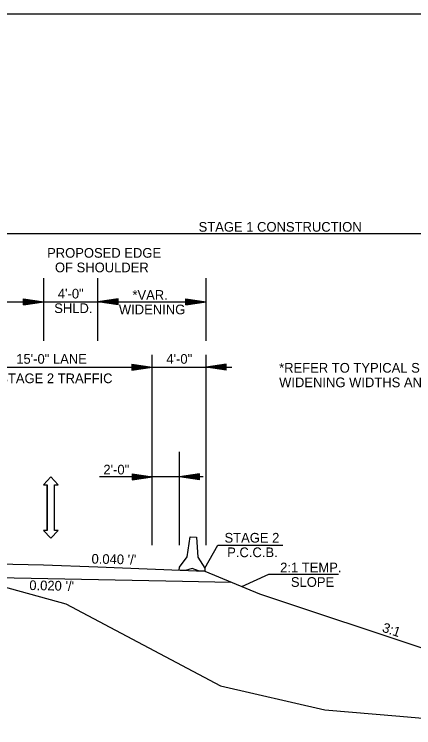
# Model space of a CAD drawing. Extents: x 1807779 to 1818251, y 673292 to 678849.
# Drawn here: x 1813576 to 1813872, y 676849 to 677379 of the extents above; entities that cross this region are included whole.
import ezdxf

# ---------------------------------------------------------------- set-up
doc = ezdxf.new("R2010")
doc.units = 0
for name, color, linetype in [('Default', 7, 'Continuous'), ('Dimensions', 7, 'Continuous'), ('DSN_DRFT_Guideline-No-Plot', 7, 'Continuous'), ('EX_TERRAIN', 7, 'Continuous'), ('Level 1', 7, 'Continuous')]:
    doc.layers.add(name, color=color, linetype=linetype)

msp = doc.modelspace()

# ---------------------------------------------------------------- linework, layer by layer
at = {"layer": 'Default'}
for p, q in [((1813487.67, 676972.49), (1813597.65, 676970.29)), ((1813597.65, 676970.29), (1813637.9, 676968.68)), ((1813637.9, 676968.68), (1813717.07, 676965.51)), ((1813717.07, 676965.51), (1813757.78, 676948.7)), ((1813487.67, 676962.49), (1813700.59, 676958.23)), ((1813700.59, 676958.23), (1813736.44, 676957.51)), ((1813757.78, 676948.7), (1814046.76, 676852.37))]:
    msp.add_line(p, q, dxfattribs=at)
at = {"layer": 'Dimensions'}
for p, q in [((1813487.67, 677216.24), (1814046.76, 677216.24)), ((1813597.67, 677136.5), (1813597.67, 677183.13)), ((1813637.9, 677136.5), (1813637.9, 677183.13)), ((1813718.05, 677136.5), (1813718.05, 677183.13)), ((1813582.67, 677167.67), (1813597.67, 677165.42)), ((1813582.67, 677163.17), (1813582.67, 677167.67)), ((1813582.67, 677167.29), (1813595.17, 677165.42)), ((1813582.67, 677166.91), (1813592.59, 677165.42)), ((1813582.67, 677166.54), (1813590.09, 677165.42)), ((1813582.67, 677166.15), (1813587.55, 677165.42)), ((1813582.67, 677165.77), (1813585.04, 677165.42)), ((1813652.9, 677167.67), (1813637.9, 677165.42)), ((1813652.9, 677167.29), (1813640.41, 677165.42)), ((1813652.9, 677166.91), (1813642.99, 677165.42)), ((1813652.9, 677166.54), (1813645.48, 677165.42)), ((1813652.9, 677166.15), (1813648.03, 677165.42)), ((1813652.9, 677165.77), (1813650.53, 677165.42)), ((1813652.9, 677163.17), (1813652.9, 677167.67)), ((1813703.05, 677167.67), (1813718.05, 677165.42)), ((1813703.05, 677163.17), (1813703.05, 677167.67)), ((1813703.05, 677167.29), (1813715.55, 677165.42)), ((1813703.05, 677166.91), (1813712.97, 677165.42)), ((1813703.05, 677166.54), (1813710.47, 677165.42)), ((1813703.05, 677166.15), (1813707.93, 677165.42)), ((1813703.05, 677165.77), (1813705.42, 677165.42)), ((1813487.67, 677165.42), (1813597.67, 677165.42)), ((1813582.67, 677163.17), (1813597.67, 677165.42)), ((1813582.67, 677164.69), (1813587.55, 677165.42)), ((1813582.67, 677163.93), (1813592.59, 677165.42)), ((1813582.67, 677163.54), (1813595.17, 677165.42)), ((1813582.67, 677164.3), (1813590.09, 677165.42)), ((1813582.67, 677165.07), (1813585.04, 677165.42)), ((1813597.67, 677165.42), (1813718.05, 677165.42)), ((1813652.9, 677163.17), (1813637.9, 677165.42)), ((1813652.9, 677163.54), (1813640.41, 677165.42)), ((1813652.9, 677163.93), (1813642.99, 677165.42)), ((1813652.9, 677164.3), (1813645.48, 677165.42)), ((1813652.9, 677164.69), (1813648.03, 677165.42)), ((1813652.9, 677165.07), (1813650.53, 677165.42)), ((1813703.05, 677163.17), (1813718.05, 677165.42)), ((1813703.05, 677164.69), (1813707.93, 677165.42)), ((1813703.05, 677163.93), (1813712.97, 677165.42)), ((1813703.05, 677163.54), (1813715.55, 677165.42)), ((1813703.05, 677164.3), (1813710.47, 677165.42)), ((1813703.05, 677165.07), (1813705.42, 677165.42)), ((1813678.05, 676984.76), (1813678.05, 677126.17)), ((1813718.05, 676984.76), (1813718.05, 677126.17)), ((1813663.05, 677119.2), (1813678.05, 677116.95)), ((1813663.05, 677119.2), (1813663.05, 677114.7)), ((1813663.05, 677118.82), (1813675.55, 677116.95)), ((1813663.05, 677118.44), (1813672.97, 677116.95)), ((1813663.05, 677118.07), (1813670.47, 677116.95)), ((1813733.05, 677119.2), (1813718.05, 677116.95)), ((1813733.05, 677118.82), (1813720.56, 677116.95)), ((1813733.05, 677118.44), (1813723.14, 677116.95)), ((1813733.05, 677118.07), (1813725.64, 677116.95)), ((1813733.05, 677114.7), (1813733.05, 677119.2)), ((1813528.05, 677116.95), (1813678.05, 677116.95)), ((1813663.05, 677117.68), (1813667.93, 677116.95)), ((1813663.05, 677117.3), (1813665.42, 677116.95)), ((1813663.05, 677114.7), (1813678.05, 677116.95)), ((1813663.05, 677116.21), (1813667.93, 677116.95)), ((1813663.05, 677115.46), (1813672.97, 677116.95)), ((1813663.05, 677115.07), (1813675.55, 677116.95)), ((1813663.05, 677115.83), (1813670.47, 677116.95)), ((1813663.05, 677116.6), (1813665.42, 677116.95)), ((1813678.05, 677116.95), (1813737.3, 677116.95)), ((1813733.05, 677114.7), (1813718.05, 677116.95)), ((1813733.05, 677115.07), (1813720.56, 677116.95)), ((1813733.05, 677115.46), (1813723.14, 677116.95)), ((1813733.05, 677115.83), (1813725.64, 677116.95)), ((1813733.05, 677117.68), (1813728.18, 677116.95)), ((1813733.05, 677116.22), (1813728.18, 677116.95)), ((1813733.05, 677117.3), (1813730.68, 677116.95)), ((1813733.05, 677116.6), (1813730.68, 677116.95)), ((1813698.31, 676984.76), (1813698.31, 677054.21)), ((1813715.9, 677035.48), (1813639.13, 677035.48)), ((1813663.31, 677037.73), (1813678.31, 677035.48)), ((1813663.31, 677037.73), (1813663.31, 677033.23)), ((1813663.31, 677037.36), (1813675.81, 677035.48)), ((1813663.31, 677036.98), (1813673.23, 677035.48)), ((1813663.31, 677036.6), (1813670.73, 677035.48)), ((1813663.31, 677036.21), (1813668.19, 677035.48)), ((1813663.31, 677035.84), (1813665.68, 677035.48)), ((1813663.31, 677033.23), (1813678.31, 677035.48)), ((1813663.31, 677034.75), (1813668.19, 677035.48)), ((1813663.31, 677033.99), (1813673.23, 677035.48)), ((1813663.31, 677033.61), (1813675.81, 677035.48)), ((1813663.31, 677034.37), (1813670.73, 677035.48)), ((1813663.31, 677035.13), (1813665.68, 677035.48)), ((1813713.31, 677037.73), (1813698.31, 677035.48)), ((1813713.31, 677033.23), (1813698.31, 677035.48)), ((1813713.31, 677037.36), (1813700.82, 677035.48)), ((1813713.31, 677033.61), (1813700.82, 677035.48)), ((1813713.31, 677036.98), (1813703.4, 677035.48)), ((1813713.31, 677033.99), (1813703.4, 677035.48)), ((1813713.31, 677036.6), (1813705.9, 677035.48)), ((1813713.31, 677034.37), (1813705.9, 677035.48)), ((1813713.31, 677036.22), (1813708.44, 677035.48)), ((1813713.31, 677034.76), (1813708.44, 677035.48)), ((1813713.31, 677035.84), (1813710.94, 677035.48)), ((1813713.31, 677035.13), (1813710.94, 677035.48)), ((1813713.31, 677033.23), (1813713.31, 677037.73)), ((1813600.35, 676995.86), (1813600.35, 677029.59))]:
    msp.add_line(p, q, dxfattribs=at)
for points in [[(1813605.75, 676995.86), (1813605.75, 677029.59), (1813608.45, 677029.59), (1813603.05, 677035.51), (1813597.65, 677029.59), (1813600.35, 677029.59)], [(1813600.35, 677029.59), (1813600.35, 676995.86), (1813597.65, 676995.86), (1813603.05, 676989.94), (1813608.45, 676995.86), (1813605.75, 676995.86)], [(1813717.14, 676967.86), (1813726.83, 676984.75), (1813775.05, 676984.75)], [(1813744.48, 676954.19), (1813764.72, 676963.23), (1813816.33, 676963.23)]]:
    msp.add_lwpolyline(points, dxfattribs=at)
at = {"layer": 'DSN_DRFT_Guideline-No-Plot'}
msp.add_lwpolyline([(1812650.63, 676379.88), (1814300.63, 676379.88), (1814300.63, 677378.94), (1812650.63, 677378.94)], close=True, dxfattribs=at)
at = {"layer": 'EX_TERRAIN'}
msp.add_lwpolyline([(1812678.82, 676968.89), (1812734.48, 676935.93), (1812877.87, 676880.69), (1812959.16, 676882.83), (1813053.74, 676934.27), (1813144.45, 676972.05), (1813219.03, 676974.2), (1813299.21, 676975.27), (1813459.2, 676973.13), (1813487.67, 676972.49), (1813516, 676968.9), (1813566.57, 676954.47), (1813614.02, 676941.38), (1813728.73, 676880.37), (1813806.18, 676862.53), (1813861.67, 676857.88), (1813918.12, 676853.04), (1814104.93, 676852.07), (1814246.73, 676850.15)], dxfattribs=at)
at = {"layer": 'Level 1'}
for p, q in [((1813704.11, 676976.24), (1813706.28, 676991.09)), ((1813706.28, 676991.09), (1813710.99, 676990.9)), ((1813710.99, 676990.9), (1813711.96, 676975.93)), ((1813698.31, 676968.62), (1813704.11, 676976.24)), ((1813711.96, 676975.93), (1813717.14, 676967.86)), ((1813698.24, 676966.26), (1813698.31, 676968.62)), ((1813702.95, 676966.07), (1813698.24, 676966.26)), ((1813707.72, 676967.45), (1813702.95, 676966.07)), ((1813712.36, 676965.7), (1813707.72, 676967.45)), ((1813717.07, 676965.51), (1813712.36, 676965.7)), ((1813717.14, 676967.86), (1813717.07, 676965.51))]:
    msp.add_line(p, q, dxfattribs=at)

# ---------------------------------------------------------------- texts
at = {"layer": 'Dimensions'}
for s, p in [('STAGE 1 CONSTRUCTION', (1813712.56, 677217.53)), ('PROPOSED EDGE ', (1813600.22, 677198.22)), ('OF SHOULDER', (1813606.04, 677187.42)), ('4\'-0" ', (1813608.19, 677167.97)), ('*VAR.', (1813663.47, 677167.01)), ('SHLD. ', (1813605.5, 677157.17)), ('WIDENING', (1813653.45, 677156.21)), ('15\'-0" LANE', (1813577.34, 677119.5)), ('4\'-0"', (1813688.63, 677119.5)), ('*REFER TO TYPICAL SECTIONS FOR ', (1813772.25, 677112.9)), ('STAGE 2 TRAFFIC', (1813564.74, 677105.1)), ('WIDENING WIDTHS AND LOCATIONS.', (1813772.25, 677102.1)), ('2\'-0"', (1813641.94, 677037.34)), ('STAGE 2', (1813731.77, 676986.75)), ('P.C.C.B.', (1813733.75, 676975.95)), ('2:1 TEMP. ', (1813773.02, 676964.7)), ('SLOPE', (1813780.97, 676953.9))]:
    msp.add_text(s, height=7.2, dxfattribs=at).set_placement(p)
for s, rotation, p in [("0.040 '/'", 358.8777, (1813633.11, 676971.16)), ("0.020 '/'", 358.7593, (1813586.96, 676951.58)), ('3:1', 341.6876, (1813848.13, 676920.74))]:
    msp.add_text(s, height=7.2, rotation=rotation, dxfattribs=at).set_placement(p)

doc.saveas('drawing.dxf')
